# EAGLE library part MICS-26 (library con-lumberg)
CONNECTOR
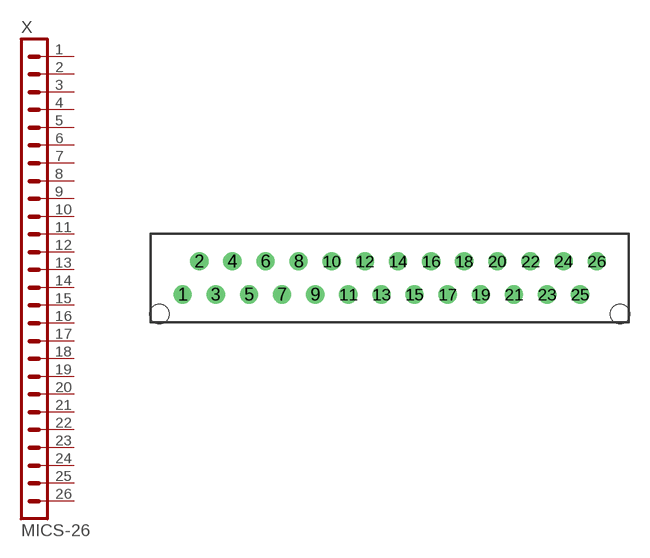
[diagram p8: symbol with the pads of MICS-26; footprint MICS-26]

Designator prefix X

## MICS-26 (OC_FARNELL: unknown; OC_NEWARK: unknown)  [MICS-26]
1  1  pas
2  2  pas
3  3  pas
4  4  pas
5  5  pas
6  6  pas
7  7  pas
8  8  pas
9  9  pas
10  10  pas
11  11  pas
12  12  pas
13  13  pas
14  14  pas
15  15  pas
16  16  pas
17  17  pas
18  18  pas
19  19  pas
20  20  pas
21  21  pas
22  22  pas
23  23  pas
24  24  pas
25  25  pas
26  26  pas

## Footprint MICS-26 (pad centres in mm)
CONNECTOR
drill 0.85 pad 1.397 round: 1 -15.875,-1.27; 2 -14.605,1.27; 3 -13.335,-1.27; 4 -12.065,1.27; 5 -10.795,-1.27; 6 -9.525,1.27; 7 -8.255,-1.27; 8 -6.985,1.27; 9 -5.715,-1.27; 10 -4.445,1.27; 11 -3.175,-1.27; 12 -1.905,1.27; 13 -0.635,-1.27; 14 0.635,1.27; 15 1.905,-1.27; 16 3.175,1.27; 17 4.445,-1.27; 18 5.715,1.27; 19 6.985,-1.27; 20 8.255,1.27; 21 9.525,-1.27; 22 10.795,1.27; 23 12.065,-1.27; 24 13.335,1.27; 25 14.605,-1.27; 26 15.875,1.27
hole 1.5 at 17.675,-2.75
hole 1.5 at -17.675,-2.75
